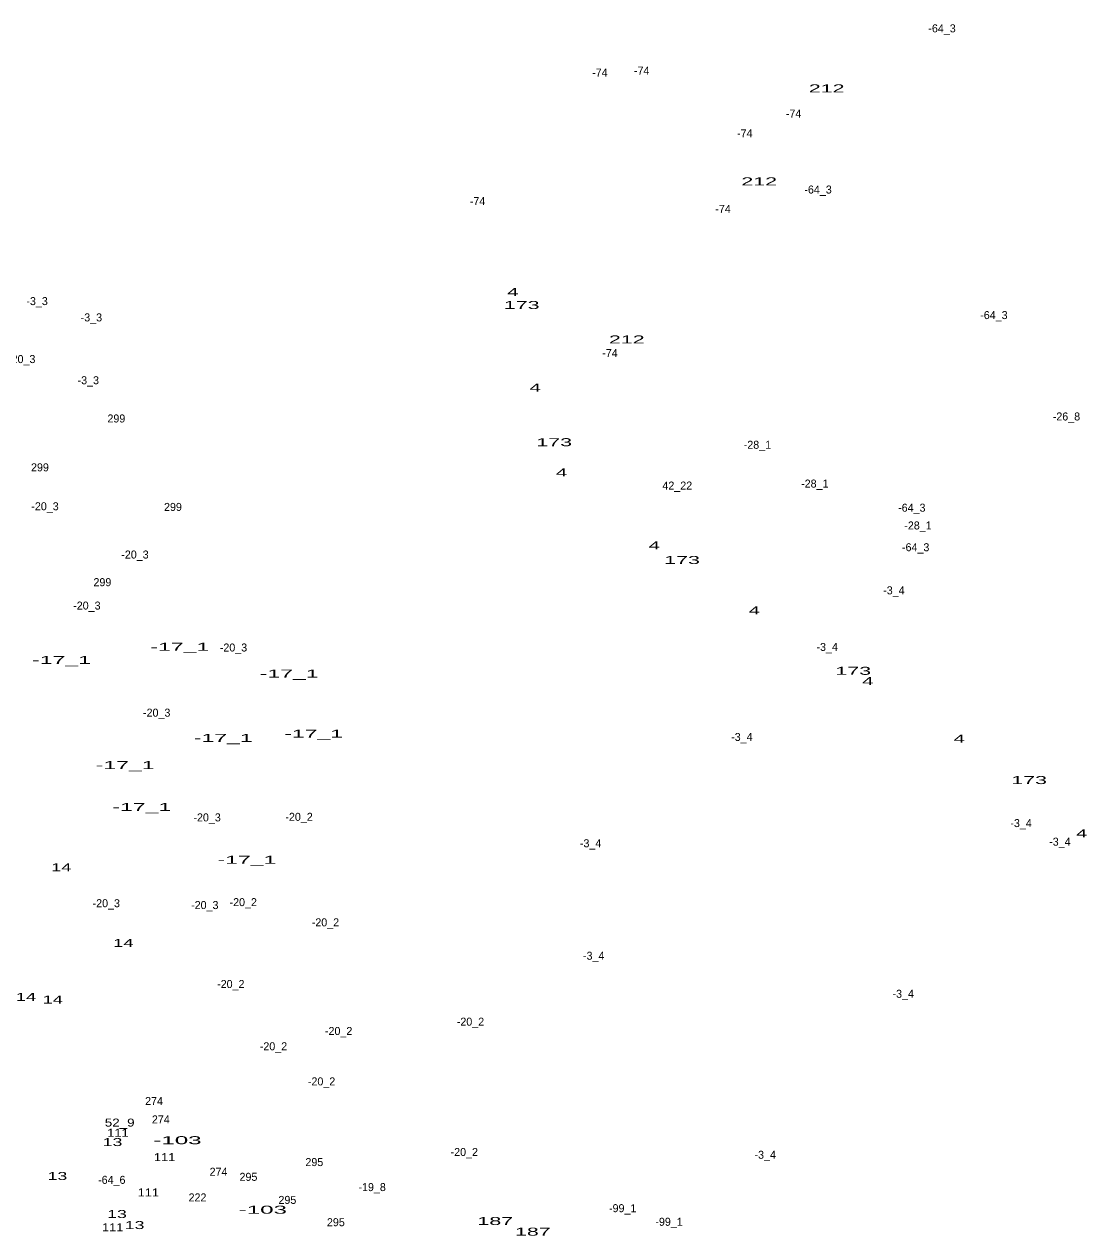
# Model space of a CAD drawing. Extents: x -656096 to -652763, y -1002270 to -998958.
# Drawn here: x -654064 to -653532, y -1001606 to -1001000 of the extents above; entities that cross this region are included whole.
import ezdxf
from ezdxf.enums import TextEntityAlignment as Align

# ---------------------------------------------------------------- set-up
doc = ezdxf.new("R2010")
doc.units = 0
doc.header["$LTSCALE"] = 1.6
doc.layers.add('24', color=7, linetype='Continuous')

msp = doc.modelspace()

# ---------------------------------------------------------------- texts
at = {"layer": '24'}
for s, p in [('-64_3', (-653604.732, -1001004.46)), ('-74', (-653775.755, -1001026.54)), ('-74', (-653754.845, -1001025.55)), ('-74', (-653678.945, -1001047.08)), ('-74', (-653703.335, -1001056.93)), ('-64_3', (-653666.702, -1001085.04)), ('-74', (-653836.945, -1001090.85)), ('-74', (-653714.185, -1001094.73)), ('-3_3', (-654057.103, -1001140.81)), ('-3_3', (-654029.963, -1001148.96)), ('-64_3', (-653578.792, -1001147.8)), ('-74', (-653770.725, -1001166.78)), ('-20_3', (-654064.786, -1001169.79)), ('-3_3', (-654031.513, -1001180.38)), ('-26_8', (-653542.538, -1001198.49)), ('299', (-654017.478, -1001199.49)), ('-28_1', (-653697.016, -1001212.64)), ('299', (-654055.678, -1001223.92)), ('42_22', (-653737.07, -1001233.03)), ('-28_1', (-653668.326, -1001232.03)), ('-20_3', (-654053.146, -1001243.38)), ('299', (-653989.178, -1001243.71)), ('-64_3', (-653619.842, -1001244.1)), ('-28_1', (-653616.756, -1001252.98)), ('-64_3', (-653617.902, -1001263.86)), ('-20_3', (-654008.176, -1001267.51)), ('299', (-654024.458, -1001281.33)), ('-3_4', (-653628.798, -1001285.4)), ('-20_3', (-654032.216, -1001293.03)), ('-20_3', (-653958.926, -1001313.99)), ('-3_4', (-653662.148, -1001313.71)), ('-20_3', (-653997.316, -1001346.56)), ('-3_4', (-653704.798, -1001358.71)), ('-20_3', (-653972.116, -1001398.92)), ('-20_2', (-653926.146, -1001398.64)), ('-3_4', (-653565.208, -1001401.76)), ('-3_4', (-653545.828, -1001411.07)), ('-3_4', (-653780.408, -1001411.85)), ('-20_2', (-653954.056, -1001441.3)), ('-20_3', (-654022.516, -1001441.83)), ('-20_3', (-653973.276, -1001442.75)), ('-20_2', (-653912.956, -1001451.39)), ('-3_4', (-653778.858, -1001468.09)), ('-20_2', (-653960.266, -1001482.22)), ('-3_4', (-653624.148, -1001487.1)), ('-20_2', (-653840.456, -1001501.04)), ('-20_2', (-653906.366, -1001505.69)), ('-20_2', (-653938.936, -1001513.34)), ('-20_2', (-653914.896, -1001530.9)), ('274', (-653998.647, -1001540.71)), ('274', (-653995.257, -1001549.91)), ('-20_2', (-653843.556, -1001566.2)), ('-3_4', (-653693.128, -1001567.58)), ('295', (-653918.513, -1001571.24)), ('-64_6', (-654019.768, -1001580.12)), ('274', (-653966.407, -1001576.06)), ('295', (-653951.443, -1001578.61)), ('-19_8', (-653889.612, -1001583.74)), ('222', (-653976.917, -1001588.9)), ('295', (-653931.983, -1001590.15)), ('-99_1', (-653764.357, -1001594.29)), ('295', (-653907.753, -1001601.3)), ('-99_1', (-653741.187, -1001601.08))]:
    msp.add_text(s, height=4, dxfattribs=at).set_placement(p, align=Align.CENTER)
for s, width, p in [('212', 2, (-653662.417, -1001034.47)), ('212', 2, (-653696.117, -1001080.96)), ('4', 1.9, (-653819.307, -1001136.3)), ('173', 2, (-653814.853, -1001142.78)), ('212', 2, (-653762.337, -1001159.99)), ('4', 1.9, (-653808.067, -1001184.01)), ('173', 2, (-653798.593, -1001211.35)), ('4', 1.9, (-653794.877, -1001226.48)), ('4', 1.9, (-653748.547, -1001262.94)), ('173', 2, (-653734.693, -1001270.24)), ('4', 1.9, (-653698.527, -1001295.4)), ('-17_1', 2.15, (-653985.753, -1001313.64)), ('-17_1', 2.15, (-654044.883, -1001320.23)), ('173', 2, (-653649.103, -1001325.64)), ('-17_1', 2.15, (-653931.083, -1001327.02)), ('4', 1.9, (-653641.837, -1001330.81)), ('-17_1', 2.15, (-653964.033, -1001359.19)), ('-17_1', 2.15, (-653918.863, -1001357.08)), ('4', 1.9, (-653596.087, -1001359.52)), ('-17_1', 2.15, (-654013.083, -1001372.79)), ('173', 2, (-653561.193, -1001380.26)), ('-17_1', 2.15, (-654004.753, -1001393.74)), ('4', 1.9, (-653534.907, -1001406.92)), ('-17_1', 2.15, (-653952.213, -1001420.11)), ('14', 1.7, (-654044.983, -1001423.85)), ('14', 1.7, (-654013.973, -1001461.67)), ('14', 1.7, (-654062.633, -1001488.63)), ('14', 1.7, (-654049.253, -1001489.99)), ('52_9', 1.25, (-654015.819, -1001551.49)), ('13', 1.65, (-654019.387, -1001561.23)), ('111', 1.2, (-654016.7, -1001556.58)), ('-103', 2.25, (-653986.927, -1001560.3)), ('111', 1.2, (-653993.36, -1001568.78)), ('13', 1.65, (-654046.927, -1001578.2)), ('111', 1.2, (-654001.5, -1001586.41)), ('13', 1.65, (-654017.167, -1001597.2)), ('-103', 2.25, (-653944.247, -1001595.05)), ('111', 1.2, (-654019.31, -1001603.84)), ('13', 1.65, (-654008.347, -1001602.73)), ('187', 2, (-653828.063, -1001600.7)), ('187', 2, (-653809.283, -1001606.02))]:
    msp.add_text(s, height=4, dxfattribs=dict(at, width=width)).set_placement(p, align=Align.CENTER)

doc.saveas('drawing.dxf')
